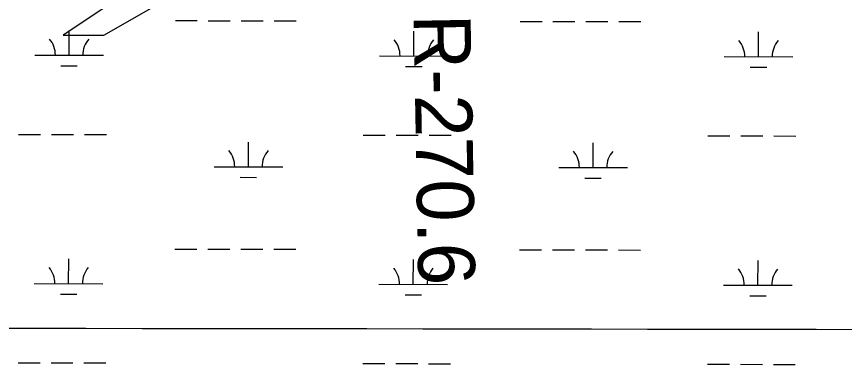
# Model space of a CAD drawing. Extents: x 3219052 to 3256913, y 800770 to 826146.
# Drawn here: x 3230665 to 3231870, y 818244 to 818751 of the extents above; entities that cross this region are included whole.
import ezdxf

# ---------------------------------------------------------------- set-up
doc = ezdxf.new("R2010")
doc.units = 0
for name, color, linetype in [('V-GRID-MAJR', 7, 'Continuous'), ('V-RIVR-RANG-IDEN', 7, 'Continuous'), ('V-TOPO-SHOR', 7, 'Continuous'), ('V-WETL-SWMP', 7, 'Continuous')]:
    doc.layers.add(name, color=color, linetype=linetype)

msp = doc.modelspace()

# ---------------------------------------------------------------- linework, layer by layer
at = {"layer": 'V-GRID-MAJR'}
msp.add_spline([(3223238.921, 818307.868), (3228474.772, 818299.872), (3233710.625, 818292.637), (3238946.4790000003, 818286.164), (3244182.3340000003, 818280.452), (3249418.1890000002, 818275.502), (3254654.045, 818271.314), (3254654.046, 818271.314)], degree=3, dxfattribs=at)
at = {"layer": 'V-TOPO-SHOR'}
msp.add_lwpolyline([(3230791.6723272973, 818762.9004740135), (3230732.3668556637, 818723.5427853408), (3230791.589576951, 818723.418659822), (3230860.7655021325, 818762.7556609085)], dxfattribs=at)
at = {"layer": 'V-WETL-SWMP'}
for p, q in [((3230895.818796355, 818744.6652166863), (3230927.818726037, 818744.5981477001)), ((3230943.818690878, 818744.5646132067), (3230975.81862056, 818744.497544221)), ((3230991.8185854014, 818744.4640097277), (3231023.8185150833, 818744.3969407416)), ((3231039.818479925, 818744.3634062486), (3231071.818409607, 818744.2963372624)), ((3231397.7256934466, 818743.6132647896), (3231429.725623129, 818743.5461958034)), ((3231445.7255879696, 818743.51266131), (3231477.725517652, 818743.4455923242)), ((3231493.7254824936, 818743.4120578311), (3231525.725412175, 818743.3449888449)), ((3231541.7253770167, 818743.3114543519), (3231573.725306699, 818743.2443853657)), ((3230741.120788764, 818694.247383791), (3230741.196239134, 818730.2472725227)), ((3231243.027685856, 818693.1954318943), (3231243.1031362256, 818729.195320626)), ((3231744.9345829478, 818692.1434799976), (3231745.010033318, 818728.1433687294)), ((3230691.120898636, 818694.3521790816), (3230791.1206788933, 818694.1425885)), ((3231193.027795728, 818693.300227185), (3231293.027575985, 818693.0906366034)), ((3231694.9346928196, 818692.2482752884), (3231794.934473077, 818692.0386847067)), ((3230729.088474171, 818678.8415823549), (3230753.0884214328, 818678.7912806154)), ((3231230.9953712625, 818677.7896304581), (3231254.9953185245, 818677.7393287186)), ((3231732.9022683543, 818676.7376785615), (3231756.9022156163, 818676.687376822)), ((3230667.4710226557, 818578.9695968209), (3230699.470952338, 818578.9025278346)), ((3230715.4709171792, 818578.8689933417), (3230747.470846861, 818578.8019243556)), ((3230763.470811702, 818578.7683898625), (3230795.4707413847, 818578.7013208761)), ((3231169.3779197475, 818577.9176449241), (3231201.3778494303, 818577.850575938)), ((3231217.377814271, 818577.817041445), (3231249.377743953, 818577.7499724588)), ((3231265.3777087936, 818577.7164379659), (3231297.3776384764, 818577.6493689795)), ((3231671.2848168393, 818576.8656930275), (3231703.284746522, 818576.7986240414)), ((3231719.284711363, 818576.7650895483), (3231751.2846410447, 818576.6980205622)), ((3231767.2846058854, 818576.6644860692), (3231799.284535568, 818576.5974170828)), ((3231002.216976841, 818531.8379388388), (3231002.2924272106, 818567.8378275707)), ((3231504.1238739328, 818530.7859869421), (3231504.1993243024, 818566.785875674)), ((3230952.217086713, 818531.9427341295), (3231052.216866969, 818531.7331435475)), ((3231454.1239838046, 818530.8907822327), (3231554.123764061, 818530.6811916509)), ((3230990.1846622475, 818516.4321374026), (3231014.184609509, 818516.3818356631)), ((3231492.09155934, 818515.3801855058), (3231516.091506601, 818515.3298837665)), ((3230895.1215615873, 818411.9912449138), (3230927.121491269, 818411.9241759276)), ((3230943.12145611, 818411.8906414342), (3230975.1213857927, 818411.8235724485)), ((3230991.121350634, 818411.7900379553), (3231023.121280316, 818411.7229689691)), ((3231039.1212451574, 818411.6894344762), (3231071.121174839, 818411.62236549)), ((3231397.028458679, 818410.9392930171), (3231429.028388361, 818410.872224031)), ((3231445.028353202, 818410.8386895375), (3231477.0282828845, 818410.7716205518)), ((3231493.0282477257, 818410.7380860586), (3231525.028177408, 818410.6710170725)), ((3231541.028142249, 818410.6374825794), (3231573.028071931, 818410.5704135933)), ((3230740.4235539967, 818361.5734120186), (3230740.499004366, 818397.5733007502)), ((3231242.3304510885, 818360.5214601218), (3231242.4059014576, 818396.5213488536)), ((3231744.2373481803, 818359.4695082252), (3231744.31279855, 818395.469396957)), ((3230690.423663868, 818361.6782073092), (3230790.4234441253, 818361.4686167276)), ((3231192.33056096, 818360.6262554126), (3231292.330341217, 818360.416664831)), ((3231694.2374580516, 818359.574303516), (3231794.237238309, 818359.3647129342)), ((3230728.3912394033, 818346.1676105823), (3230752.391186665, 818346.117308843)), ((3231230.298136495, 818345.1156586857), (3231254.2980837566, 818345.0653569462)), ((3231732.205033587, 818344.063706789), (3231756.2049808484, 818344.0134050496)), ((3230666.773787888, 818246.2956250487), (3230698.7737175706, 818246.2285560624)), ((3230714.7736824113, 818246.1950215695), (3230746.7736120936, 818246.1279525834)), ((3230762.773576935, 818246.0944180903), (3230794.7735066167, 818246.0273491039)), ((3231168.68068498, 818245.2436731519), (3231200.6806146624, 818245.1766041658)), ((3231216.680579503, 818245.1430696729), (3231248.6805091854, 818245.0760006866)), ((3231264.6804740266, 818245.0424661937), (3231296.6804037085, 818244.9753972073)), ((3231670.587582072, 818244.1917212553), (3231702.587511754, 818244.1246522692)), ((3231718.587476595, 818244.0911177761), (3231750.587406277, 818244.02404879)), ((3231766.587371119, 818243.990514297), (3231798.5873008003, 818243.9234453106))]:
    msp.add_line(p, q, dxfattribs=at)
for centre, radius, start, end in [((3230685.878969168, 818694.8379694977), 35.24628790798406, 359.1080939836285, 40.65175231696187), ((3230796.364598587, 818694.6064015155), 35.246287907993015, 139.10808960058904, 180.65174793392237), ((3231187.7858662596, 818693.786017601), 35.24628790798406, 359.1080939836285, 40.65175231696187), ((3231298.271495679, 818693.5544496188), 35.246287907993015, 139.10808960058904, 180.65174793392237), ((3231689.6927633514, 818692.7340657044), 35.24628790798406, 359.1080939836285, 40.65175231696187), ((3231800.1783927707, 818692.5024977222), 35.246287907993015, 139.10808960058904, 180.65174793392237), ((3230946.9751572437, 818532.4285245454), 35.24628790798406, 359.1080939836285, 40.65175231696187), ((3231057.460786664, 818532.1969565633), 35.246287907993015, 139.10808960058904, 180.65174793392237), ((3231448.8820543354, 818531.3765726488), 35.24628790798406, 359.1080939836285, 40.65175231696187), ((3231559.367683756, 818531.1450046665), 35.246287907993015, 139.10808960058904, 180.65174793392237), ((3230685.1817344, 818362.1639977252), 35.24628790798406, 359.1080939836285, 40.65175231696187), ((3230795.6673638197, 818361.9324297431), 35.246287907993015, 139.10808960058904, 180.65174793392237), ((3231187.0886314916, 818361.1120458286), 35.24628790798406, 359.1080939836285, 40.65175231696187), ((3231297.5742609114, 818360.8804778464), 35.246287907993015, 139.10808960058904, 180.65174793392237), ((3231688.9955285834, 818360.060093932), 35.24628790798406, 359.1080939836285, 40.65175231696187), ((3231799.481158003, 818359.8285259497), 35.246287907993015, 139.10808960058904, 180.65174793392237)]:
    msp.add_arc(centre, radius, start, end, dxfattribs=at)

# ---------------------------------------------------------------- texts
at = {"layer": 'V-RIVR-RANG-IDEN'}
msp.add_text('R-270.6', height=82.99999799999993, rotation=271.0295697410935, dxfattribs=at).set_placement((3231242.647, 818753.464))

doc.saveas('drawing.dxf')
